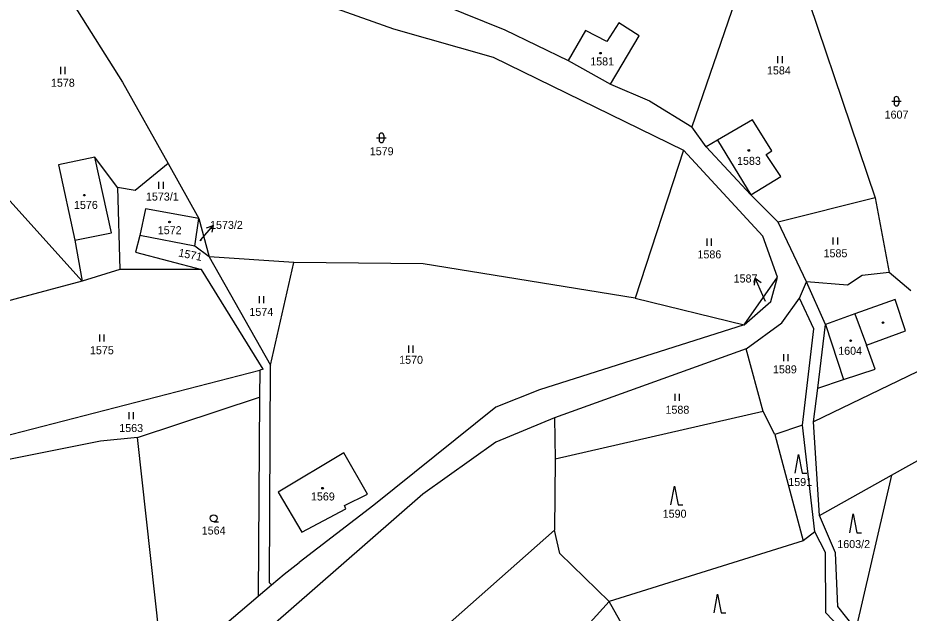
# Model space of a CAD drawing. Extents: x -670359 to -668019, y -978807 to -976674.
# Drawn here: x -669348.5 to -669159.3, y -978050.6 to -977924.2 of the extents above; entities that cross this region are included whole.
import ezdxf

# ---------------------------------------------------------------- set-up
doc = ezdxf.new("R2010")
doc.units = 0
for name, color, linetype in [('Hranice parcel', 7, 'Continuous'), ('Parcelní čísla', 7, 'Continuous'), ('Vnitřní kresba', 7, 'Continuous'), ('Značky budov', 7, 'Continuous'), ('Značky kultur', 7, 'Continuous')]:
    doc.layers.add(name, color=color, linetype=linetype)

msp = doc.modelspace()

# ---------------------------------------------------------------- linework, layer by layer
at = {"layer": 'Hranice parcel'}
for points in [[(-669190.85, -977904.86), (-669205.42, -977947.35)], [(-669185.66, -977905.56), (-669166.49, -977962.39)], [(-669289.69, -977908.65), (-669245.12, -977926.75)], [(-669339.55, -977916.69), (-669326.24, -977937.87)], [(-669295.28, -977917.01), (-669268.73, -977926.5)], [(-669220.93, -977925.25), (-669223.45, -977929.22)], [(-669216.55, -977928.02), (-669220.93, -977925.25)], [(-669268.73, -977926.5), (-669247.58, -977932.56)], [(-669245.12, -977926.75), (-669231.66, -977933.22)], [(-669227.99, -977926.86), (-669231.66, -977933.22)], [(-669223.45, -977929.22), (-669227.99, -977926.86)], [(-669222.66, -977938.27), (-669216.55, -977928.02)], [(-669247.58, -977932.56), (-669207.2, -977952.28)], [(-669231.66, -977933.22), (-669222.66, -977938.27)], [(-669326.24, -977937.87), (-669316.58, -977955.09)], [(-669222.66, -977938.27), (-669214.4, -977941.84)], [(-669214.4, -977941.84), (-669205.42, -977947.35)], [(-669192.49, -977945.88), (-669199.98, -977950.19)], [(-669188.39, -977952.4), (-669192.49, -977945.88)], [(-669202.38, -977951.58), (-669205.42, -977947.35)], [(-669199.98, -977950.19), (-669202.38, -977951.58)], [(-669207.2, -977952.28), (-669217.46, -977983.76)], [(-669190.35, -977970.56), (-669207.2, -977952.28)], [(-669192.85, -977961.76), (-669202.38, -977951.58)], [(-669189.6, -977953.19), (-669188.39, -977952.4)], [(-669334.85, -977980.09), (-669358.51, -977953.84)], [(-669332.17, -977953.81), (-669339.88, -977955.4)], [(-669327.3, -977960.23), (-669332.17, -977953.81)], [(-669186.53, -977957.86), (-669189.6, -977953.19)], [(-669339.88, -977955.4), (-669336.36, -977971.44)], [(-669316.58, -977955.09), (-669323.6, -977960.86)], [(-669316.58, -977955.09), (-669310.06, -977966.84)], [(-669192.85, -977961.76), (-669186.53, -977957.86)], [(-669323.6, -977960.86), (-669327.3, -977960.23)], [(-669327.3, -977960.23), (-669326.82, -977977.66)], [(-669187.04, -977967.6), (-669192.85, -977961.76)], [(-669166.49, -977962.39), (-669187.04, -977967.6)], [(-669166.49, -977962.39), (-669163.53, -977978.26)], [(-669321.4, -977964.72), (-669322.58, -977970.39)], [(-669310.06, -977966.84), (-669321.4, -977964.72)], [(-669310.92, -977972.67), (-669310.06, -977966.84)], [(-669310.06, -977966.84), (-669307.9, -977974.94)], [(-669181.08, -977980.23), (-669187.04, -977967.6)], [(-669322.58, -977970.39), (-669323.5, -977973.98)], [(-669310.92, -977972.67), (-669322.58, -977970.39)], [(-669187.18, -977979.26), (-669190.35, -977970.56)], [(-669336.36, -977971.44), (-669334.85, -977980.09)], [(-669307.9, -977974.94), (-669310.92, -977972.67)], [(-669323.5, -977973.98), (-669309.53, -977977.65)], [(-669289.9, -977976.18), (-669307.9, -977974.94)], [(-669307.9, -977974.94), (-669294.82, -977997.96)], [(-669294.82, -977997.96), (-669289.9, -977976.18)], [(-669262.45, -977976.47), (-669289.9, -977976.18)], [(-669217.46, -977983.76), (-669262.45, -977976.47)], [(-669326.82, -977977.66), (-669334.85, -977980.09)], [(-669309.53, -977977.65), (-669326.82, -977977.66)], [(-669296.39, -977998.82), (-669309.53, -977977.65)], [(-669163.53, -977978.26), (-669169.22, -977978.92)], [(-669158.93, -977982.15), (-669163.53, -977978.26)], [(-669334.85, -977980.09), (-669356.37, -977985.86)], [(-669194.31, -977989.37), (-669187.18, -977979.26)], [(-669188.65, -977984.47), (-669187.18, -977979.26)], [(-669182.56, -977983.74), (-669181.08, -977980.23)], [(-669172.37, -977980.97), (-669181.08, -977980.23)], [(-669177.02, -977989.31), (-669181.08, -977980.23)], [(-669169.22, -977978.92), (-669172.37, -977980.97)], [(-669217.46, -977983.76), (-669194.31, -977989.37)], [(-669194.31, -977989.37), (-669188.65, -977984.47)], [(-669186.3, -977988.97), (-669182.56, -977983.74)], [(-669179.51, -977990.25), (-669182.56, -977983.74)], [(-669162.23, -977984.03), (-669170.79, -977987.09)], [(-669160.06, -977990.7), (-669162.23, -977984.03)], [(-669170.79, -977987.09), (-669177.02, -977989.31)], [(-669194.31, -977989.37), (-669237.73, -978003.18)], [(-669193.88, -977994.49), (-669186.3, -977988.97)], [(-669181.88, -978010.7), (-669179.51, -977990.25)], [(-669178.68, -978002.85), (-669177.02, -977989.31)], [(-669168.34, -977993.73), (-669160.06, -977990.7)], [(-669166.47, -977998.79), (-669168.34, -977993.73)], [(-669193.88, -977994.49), (-669234.54, -978009.17)], [(-669190.26, -978007.81), (-669193.88, -977994.49)], [(-669147.61, -977994.59), (-669179.56, -978010)], [(-669365.21, -978016.55), (-669297.15, -977999.02)], [(-669297.15, -977999.02), (-669297.19, -978004.74)], [(-669296.39, -977998.82), (-669297.15, -977999.02)], [(-669295.03, -978044.16), (-669294.82, -977997.96)], [(-669173.22, -978001.03), (-669166.47, -977998.79)], [(-669162.99, -978021.31), (-669123.02, -977998.99)], [(-669178.68, -978002.85), (-669173.22, -978001.03)], [(-669237.73, -978003.18), (-669247.03, -978006.9)], [(-669179.56, -978010), (-669178.68, -978002.85)], [(-669323.12, -978013.33), (-669297.19, -978004.74)], [(-669297.19, -978004.74), (-669297.45, -978047.05)], [(-669247.03, -978006.9), (-669272.9, -978027.73)], [(-669234.54, -978009.17), (-669247.03, -978014.3)], [(-669234.54, -978009.17), (-669234.39, -978017.89)], [(-669190.26, -978007.81), (-669234.39, -978017.89)], [(-669187.75, -978012.71), (-669190.26, -978007.81)], [(-669181.88, -978010.7), (-669187.75, -978012.71)], [(-669179.29, -978033.35), (-669181.88, -978010.7)], [(-669178.32, -978029.87), (-669179.56, -978010)], [(-669187.75, -978012.71), (-669181.74, -978035.25)], [(-669330.97, -978014.13), (-669360.73, -978020.04)], [(-669323.12, -978013.33), (-669330.97, -978014.13)], [(-669317.49, -978064.1), (-669323.12, -978013.33)], [(-669247.03, -978014.3), (-669262.52, -978025.33)], [(-669279.28, -978016.6), (-669293.22, -978024.93)], [(-669274.25, -978025.38), (-669279.28, -978016.6)], [(-669234.39, -978017.89), (-669234.55, -978033)], [(-669178.32, -978029.87), (-669162.99, -978021.31)], [(-669162.99, -978021.31), (-669170.57, -978054.01)], [(-669293.22, -978024.93), (-669288.19, -978033.46)], [(-669262.52, -978025.33), (-669285.43, -978045.41)], [(-669279.16, -978027.8), (-669274.25, -978025.38)], [(-669272.9, -978027.73), (-669288.74, -978039.86)], [(-669278.85, -978028.45), (-669279.16, -978027.8)], [(-669288.19, -978033.46), (-669278.85, -978028.45)], [(-669174.89, -978037.81), (-669178.32, -978029.87)], [(-669234.55, -978033), (-669307.7, -978097.77)], [(-669233.4, -978037.98), (-669234.55, -978033)], [(-669179.29, -978033.35), (-669181.74, -978035.25)], [(-669177.05, -978037.78), (-669179.29, -978033.35)], [(-669181.74, -978035.25), (-669222.94, -978048.17)], [(-669222.94, -978048.17), (-669233.4, -978037.98)], [(-669176.94, -978050.58), (-669177.05, -978037.78)], [(-669174.37, -978049.25), (-669174.89, -978037.81)], [(-669291.96, -978042.38), (-669288.74, -978039.86)], [(-669294.62, -978044.64), (-669291.96, -978042.38)], [(-669297.45, -978047.05), (-669294.62, -978044.64)], [(-669294.62, -978044.64), (-669295.03, -978044.16)], [(-669285.43, -978045.41), (-669307.17, -978064.37)], [(-669317.49, -978064.1), (-669297.45, -978047.05)], [(-669280.17, -978111.46), (-669222.94, -978048.17)], [(-669214.62, -978063.05), (-669222.94, -978048.17)], [(-669171.4, -978056.4), (-669176.94, -978050.58)], [(-669170.57, -978054.01), (-669174.37, -978049.25)]]:
    msp.add_lwpolyline(points, dxfattribs=at)
at = {"layer": 'Parcelní čísla'}
for p, q in [((-669308.44, -977968.77), (-669307.03, -977968.26)), ((-669309.83, -977971.55), (-669309.62, -977971.31)), ((-669192.08, -977980.98), (-669191.92, -977979.48)), ((-669189.74, -977984.41), (-669190.3, -977983.14))]:
    msp.add_line(p, q, dxfattribs=at)
for points in [[(-669309.62, -977971.31), (-669307.03, -977968.26), (-669307.3, -977969.74)], [(-669190.3, -977983.14), (-669191.92, -977979.48), (-669190.71, -977980.37)]]:
    msp.add_lwpolyline(points, dxfattribs=at)
at = {"layer": 'Vnitřní kresba'}
for points in [[(-669199.98, -977950.19), (-669192.85, -977961.76)], [(-669328.58, -977969.84), (-669332.17, -977953.81)], [(-669336.36, -977971.44), (-669328.58, -977969.84)], [(-669170.79, -977987.09), (-669168.34, -977993.73)], [(-669177.02, -977989.31), (-669173.22, -978001.03)]]:
    msp.add_lwpolyline(points, dxfattribs=at)
at = {"layer": 'Značky budov'}
for centre in [(-669224.79, -977931.69), (-669193.3, -977952.36), (-669334.37, -977961.85), (-669316.28, -977967.54), (-669171.69, -977992.77), (-669283.8, -978024.1)]:
    msp.add_circle(centre, 0.175, dxfattribs=at)
at = {"layer": 'Značky kultur'}
for p, q in [((-669187.18, -977932.3), (-669187.18, -977933.8)), ((-669186.18, -977933.8), (-669186.18, -977932.3)), ((-669339.46, -977934.62), (-669339.46, -977936.12)), ((-669338.46, -977936.12), (-669338.46, -977934.62)), ((-669162.97, -977941.89), (-669160.97, -977941.89)), ((-669162.47, -977941.39), (-669162.47, -977942.39)), ((-669161.47, -977941.39), (-669161.47, -977942.39)), ((-669272.31, -977949.67), (-669270.31, -977949.67)), ((-669271.81, -977949.17), (-669271.81, -977950.17)), ((-669270.81, -977949.17), (-669270.81, -977950.17)), ((-669318.6, -977959.01), (-669318.6, -977960.51)), ((-669317.6, -977960.51), (-669317.6, -977959.01)), ((-669202.24, -977971.08), (-669202.24, -977972.58)), ((-669201.24, -977972.58), (-669201.24, -977971.08)), ((-669175.43, -977970.84), (-669175.43, -977972.34)), ((-669174.43, -977972.34), (-669174.43, -977970.84)), ((-669297.29, -977983.29), (-669297.29, -977984.79)), ((-669296.29, -977984.79), (-669296.29, -977983.29)), ((-669331.18, -977991.44), (-669331.18, -977992.94)), ((-669330.18, -977992.94), (-669330.18, -977991.44)), ((-669265.53, -977993.81), (-669265.53, -977995.31)), ((-669264.53, -977995.31), (-669264.53, -977993.81)), ((-669185.93, -977995.59), (-669185.93, -977997.09)), ((-669184.93, -977997.09), (-669184.93, -977995.59)), ((-669208.99, -978004.07), (-669208.99, -978005.57)), ((-669207.99, -978005.57), (-669207.99, -978004.07)), ((-669324.96, -978007.96), (-669324.96, -978009.46)), ((-669323.96, -978009.46), (-669323.96, -978007.96)), ((-669306.91, -978031.23), (-669305.91, -978031.23))]:
    msp.add_line(p, q, dxfattribs=at)
for points in [[(-669183.49, -978020.93), (-669182.74, -978016.93), (-669181.99, -978020.93), (-669180.99, -978020.93)], [(-669209.83, -978027.66), (-669209.08, -978023.66), (-669208.33, -978027.66), (-669207.33, -978027.66)], [(-669171.86, -978033.55), (-669171.11, -978029.55), (-669170.36, -978033.55), (-669169.36, -978033.55)], [(-669200.69, -978050.57), (-669199.94, -978046.57), (-669199.19, -978050.57), (-669198.19, -978050.57)]]:
    msp.add_lwpolyline(points, dxfattribs=at)
for centre, radius in [((-669224.79, -977931.69), 0.175), ((-669193.3, -977952.36), 0.175), ((-669334.37, -977961.85), 0.175), ((-669316.28, -977967.54), 0.175), ((-669164.81, -977988.93), 0.175), ((-669171.69, -977992.77), 0.175), ((-669283.8, -978024.1), 0.175), ((-669306.91, -978030.48), 0.75)]:
    msp.add_circle(centre, radius, dxfattribs=at)
for centre, start, end in [((-669161.97, -977941.39), 0, 180), ((-669161.97, -977942.39), 180, 0), ((-669271.31, -977949.17), 0, 180), ((-669271.31, -977950.17), 180, 0)]:
    msp.add_arc(centre, 0.5, start, end, dxfattribs=at)

# ---------------------------------------------------------------- texts
at = {"layer": 'Parcelní čísla'}
for s, height, p in [('1581', 1.7, (-669226.97, -977934.29)), ('1584', 1.7, (-669189.44, -977936.2)), ('1578', 1.7, (-669341.46, -977938.82)), ('1607', 1.7, (-669164.47, -977945.59)), ('1579', 1.7, (-669273.77, -977953.37)), ('1583', 1.7, (-669195.8, -977955.41)), ('1573/1', 1.7, (-669321.29, -977963)), ('1576', 1.7, (-669336.57, -977964.77)), ('1573/2', 1.7, (-669307.68, -977969.02)), ('1572', 1.7, (-669318.78, -977970.14)), ('1573/2', 0.1, (-669309.83, -977971.55)), ('1586', 1.7, (-669204.2, -977975.28)), ('1585', 1.7, (-669177.43, -977975.04)), ('1587', 1.7, (-669196.52, -977980.4)), ('1587', 0.1, (-669189.74, -977984.41)), ('1574', 1.7, (-669299.33, -977987.49)), ('1575', 1.7, (-669333.18, -977995.64)), ('1604', 1.7, (-669174.32, -977995.75)), ('1570', 1.7, (-669267.53, -977997.67)), ('1589', 1.7, (-669188.17, -977999.7)), ('1588', 1.7, (-669210.99, -978008.27)), ('1563', 1.7, (-669326.96, -978012.16)), ('1591', 1.7, (-669184.92, -978023.63)), ('1569', 1.7, (-669286.26, -978026.7)), ('1590', 1.7, (-669211.58, -978030.36)), ('1564', 1.7, (-669309.45, -978033.93)), ('1603/2', 1.7, (-669174.51, -978036.81))]:
    msp.add_text(s, height=height, dxfattribs=at).set_placement(p)
msp.add_text('1571', height=1.7, rotation=348.6091, dxfattribs=at).set_placement((-669314.5, -977974.84))

doc.saveas('drawing.dxf')
